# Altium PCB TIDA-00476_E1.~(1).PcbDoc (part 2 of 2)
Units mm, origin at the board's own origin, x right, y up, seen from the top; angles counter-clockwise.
Board outline 85.09 x 49.91 mm, 2 copper layers (Top Layer, Bottom Layer), stack 1.575 mm thick; 132 components, 75 nets, 329 pads, 292 vias.
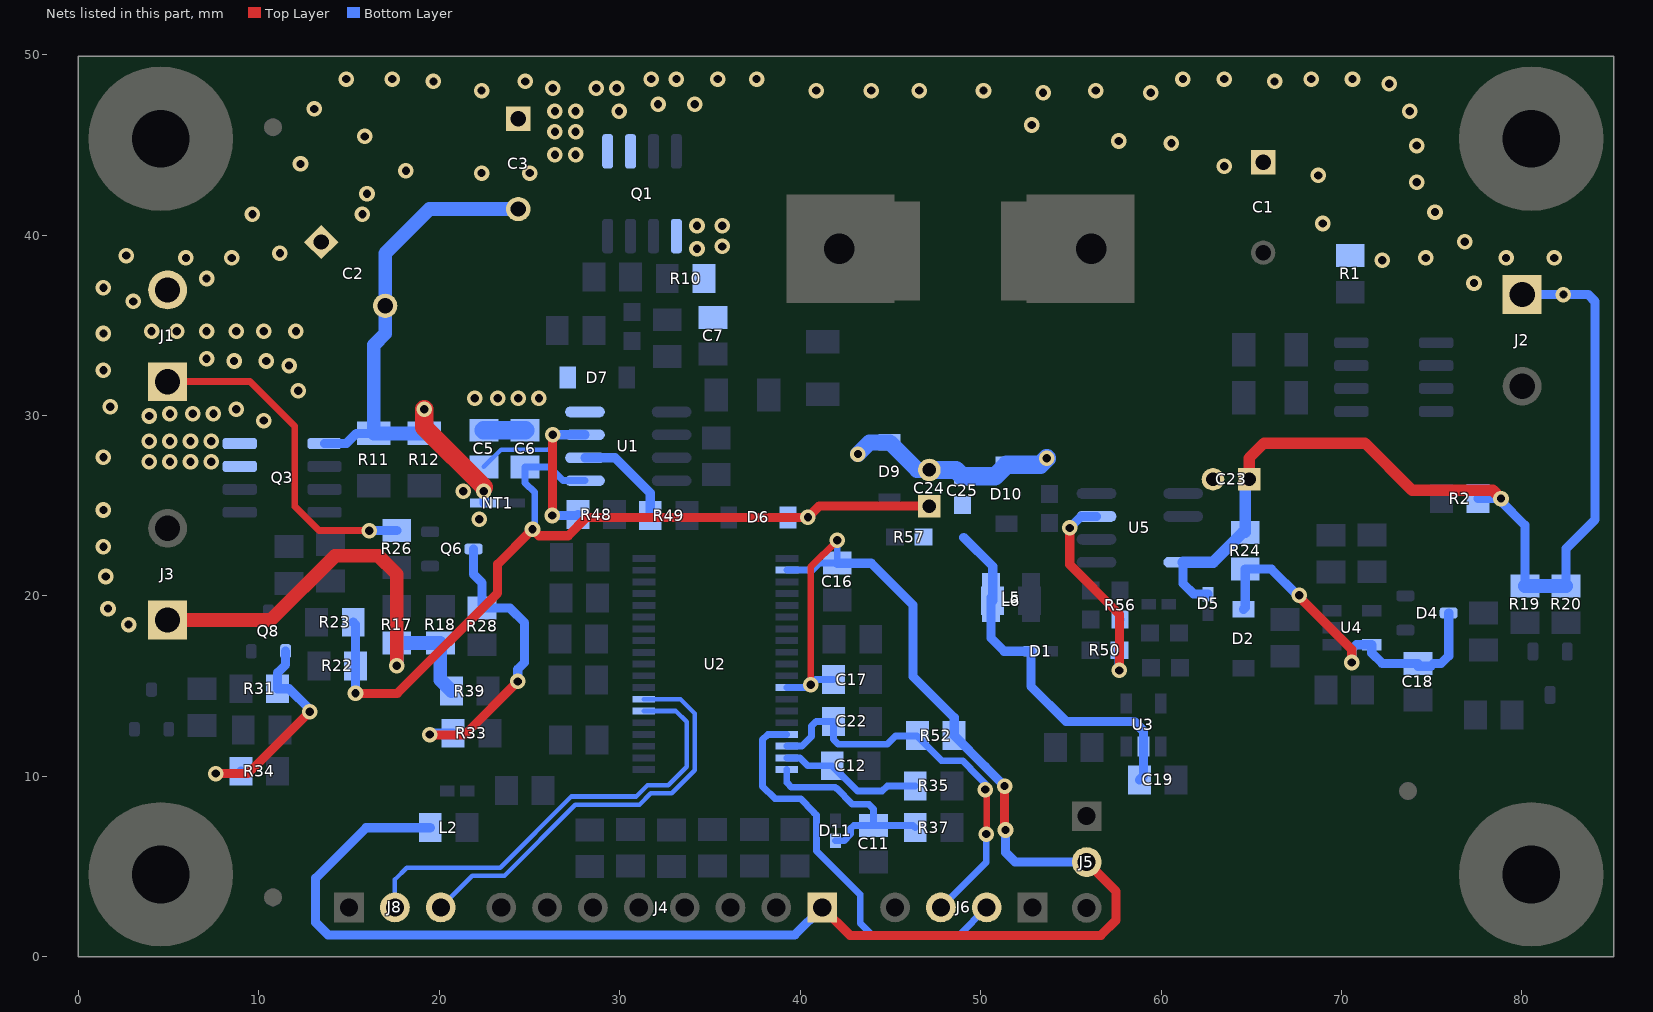
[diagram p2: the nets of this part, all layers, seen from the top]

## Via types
v1: diameter 0.864, hole 0.457, Top Layer to Bottom Layer, 292 vias

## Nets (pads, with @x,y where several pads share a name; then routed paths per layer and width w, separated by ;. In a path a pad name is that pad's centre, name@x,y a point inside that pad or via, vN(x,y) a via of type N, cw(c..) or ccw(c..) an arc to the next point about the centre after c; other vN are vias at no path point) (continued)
NetR50_2: R50.2 R56.2 U5.3 | length 13.6
  Top Layer w0.508: v1(54.939,23.774) 54.939,21.743 57.696,18.987 57.696,16.015 57.709,16.002 57.709,15.951 57.683,15.926 v1(57.683,15.875)
  Bottom Layer w0.508: v1(54.939,23.774) 55.574,24.409 U5.3@56.426,24.409 ; v1(57.683,15.875) 57.683,16.98 R50.2@57.696,16.993 57.696,18.656 R56.2@57.734,18.695
P1.1: J8.2 U2.6 | length 25.4
  Bottom Layer w0.254: J8.2@17.551,2.743 17.551,4.293 18.209,4.95 23.383,4.95 27.323,8.89 30.922,8.89 31.548,9.515 32.699,9.515 33.712,10.529 33.712,13.03 33.115,13.627 U2.6@31.339,13.627
P1.2: J8.3 U2.7 | length 23.5
  Bottom Layer w0.254: J8.3@20.091,2.743 21.844,4.496 23.622,4.496 27.553,8.426 31.101,8.426 31.736,9.061 32.887,9.061 34.166,10.341 34.166,13.487 33.376,14.277 U2.7@31.339,14.277
P1.5: C12.1 R35.2 U2.37 | length 8
  Bottom Layer w0.381: U2.37@39.263,11.029 40,11.029 40.437,10.592 C12.1@41.783,10.592 43.18,9.195 44.552,9.195 44.831,9.474 R35.2@46.38,9.474
P3.6: C11.1 D11.2 R37.1 U2.38 | length 12
  Bottom Layer w0.381: U2.38@39.263,10.376 39.263,9.657 39.519,9.401 41.927,9.401 41.981,9.347 42.012,9.347 42.901,8.458 43.815,8.458 44.069,8.204 C11.1@44.069,7.29 ; D11.2@41.961,6.435 42.427,6.435 42.799,6.807 42.799,7.112 42.977,7.29 C11.1@44.069,7.29 ; R37.1@46.38,7.163 46.253,7.29 C11.1@44.069,7.29
P+: C1.1 C2.1 C3.1 C23.1 D5.2 J1.2 J2.1 J3.1 Q1.5 Q1.6 R1.2 R2.2 R17.2 R18.2 R19.2 R20.2 R24.2 R39.1 U5.8 | length 82.7
  Top Layer w0.635: C23.1@64.881,26.467 64.881,27.645 65.71,28.473 71.298,28.473 73.914,25.857 78.384,25.857 v1(78.842,25.4)
  Top Layer w0.762: J3.1@4.953,18.669 10.668,18.669 14.224,22.225 16.637,22.225 17.653,21.209 v1(17.653,16.129)
  Bottom Layer w0.508: U5.8@61.226,21.869 61.226,20.689 61.807,20.108 D5.2@62.611,20.108 ; R2.2@77.572,25.4 78.689,25.4 v1@78.842,25.248 ; v1(78.842,25.4) v1@78.842,25.248 ; J2.1@80.01,36.703 v1(82.296,36.703) 83.671,36.703 84.052,36.322 84.052,24.235 82.448,22.631 R20.2@82.448,20.549 ; R19.2@80.162,20.549 80.162,23.927 v1@78.842,25.248
  Bottom Layer w0.635: U5.8@61.226,21.869 62.882,21.869 64.533,23.52 R24.2@64.668,23.52 64.668,26.254 C23.1@64.881,26.467
  Bottom Layer w0.762: v1(17.653,16.129) R17.2@17.653,17.399 R18.2@20.066,17.399 20.066,15.342 R39.1@20.676,14.732 ; R19.2@80.162,20.549 R20.2@82.448,20.549
  other v1: 2.794,18.415 1.651,19.304 1.524,21.082 1.397,22.733 1.397,24.765 1.397,27.686 1.778,30.48 1.397,32.512 1.397,34.544 3.048,36.322 1.397,37.084 77.343,37.338 7.112,37.592 72.263,38.608 5.969,38.735 8.509,38.735 74.676,38.735 79.121,38.735 81.788,38.735 2.667,38.862 11.176,38.989 76.835,39.624 68.961,40.64 9.652,41.148 15.748,41.148 75.184,41.275 16.002,42.291 74.168,42.926 68.707,43.307 22.352,43.434 25.019,43.434 18.161,43.561 63.5,43.815 12.319,43.942 26.416,44.45 27.559,44.45 74.168,44.958 60.579,45.085 57.658,45.212 15.875,45.466 26.416,45.72 27.559,45.72 52.832,46.101 26.416,46.863 27.559,46.863 29.972,46.863 73.787,46.863 13.081,46.99 32.131,47.244 34.163,47.244 53.467,47.879 59.436,47.879 22.352,48.006 40.894,48.006 43.942,48.006 46.609,48.006 50.165,48.006 56.388,48.006 26.289,48.133 28.702,48.133 29.845,48.133 72.644,48.387 19.685,48.514 24.765,48.514 66.294,48.514 14.859,48.641 17.399,48.641 31.75,48.641 33.147,48.641 35.433,48.641 37.592,48.641 61.214,48.641 63.5,48.641 68.326,48.641 70.612,48.641
P-: J1.1 Q3.7 Q3.8 R26.1 | length 18.7
  Top Layer w0.381: J1.1@4.953,31.877 9.525,31.877 12.002,29.4 12.002,24.956 13.335,23.622 v1(16.129,23.622)
  Bottom Layer w0.508: v1(16.129,23.622) R26.1@17.653,23.622
  other v1: 3.937,27.432 5.08,27.432 6.223,27.432 7.366,27.432 3.937,28.575 5.08,28.575 6.223,28.575 7.366,28.575 10.287,29.718 3.937,29.972 5.08,30.099 6.35,30.099 7.493,30.099 8.763,30.353 12.192,31.369 11.684,32.766 8.636,33.02 10.414,33.02 7.112,33.147 4.064,34.671 5.461,34.671 7.112,34.671 8.763,34.671 10.287,34.671 12.065,34.671
P_EN: Q8.1 R31.2 R34.1 | length 12.7
  Top Layer w0.508: v1(7.62,10.16) 9.398,10.16 v1(12.827,13.589)
  Bottom Layer w0.508: v1(7.62,10.16) 8.89,10.16 R34.1@9.017,10.287 ; Q8.1@11.491,16.934 11.491,16.19 11.049,15.748 R31.2@11.049,14.859 11.684,14.859 12.827,13.716 v1(12.827,13.589)
P_V: Q6.3 R28.2 R33.1 | length 17
  Top Layer w0.508: v1(19.482,12.319) 19.507,12.294 21.387,12.294 v1(24.359,15.265)
  Bottom Layer w0.508: v1(19.482,12.319) 19.558,12.395 R33.1@20.777,12.395 ; Q6.3@21.901,22.606 21.901,21.203 22.377,20.726 R28.2@22.377,19.329 23.927,19.329 24.736,18.52 24.736,16.321 24.359,15.943 v1(24.359,15.265)
PGND: C2.2 C3.2 C5.2 C6.2 C7.2 C23.2 C24.2 C25.2 D7.2 D9.2 D10.2 NT1.2 Q1.1 Q3.1 R10.1 R11.2 R12.2 U1.4 | length 46.5
  Top Layer w1.016: v1(19.177,30.353) 19.177,29.337 v1@22.479,26.035
  Bottom Layer w0.508: Q3.1@13.653,28.448 14.859,28.448 15.42,29.009 R11.2@16.383,29.009 ; NT1.2@22.479,25.146 v1(22.479,25.806) v1@22.479,26.035
  Bottom Layer w0.762: v1(19.177,30.353) R12.2@19.177,29.009 R11.2@16.383,29.009 16.383,33.909 17.008,34.534 C2.2@17.008,36.078 17.008,38.979 19.471,41.442 C3.2@24.384,41.442
  Bottom Layer w0.889: v1(43.205,27.864) 43.852,28.511 D9.2@44.958,28.511 46.484,26.984 C24.2@47.168,26.984
  Bottom Layer w1.016: C5.2@22.479,29.185 C6.2@24.765,29.185 ; C24.2@47.168,26.984 48.644,26.984 C25.2@48.997,26.632 50.801,26.632 D10.2@51.435,27.266 53.301,27.266 v1@53.664,27.629
  other v1: 22.225,24.257 21.336,25.806 53.67,27.635 21.971,30.963 23.241,30.963 24.384,30.963 25.527,30.963 34.29,39.243 35.687,39.37 34.29,40.513 35.687,40.513
PW_H: R49.1 U1.2 | length 5.7
  Bottom Layer w0.508: U1.2@28.08,27.661 29.744,27.661 31.699,25.705 R49.1@31.699,24.46
PW_L: C5.1 R48.1 U1.3 | length 12.6
  Top Layer w0.508: v1(26.264,24.46) 26.289,24.486 v1(26.289,28.931)
  Bottom Layer w0.254: C5.1@22.479,27.153 23.441,28.115 26.035,28.115 26.289,28.369 v1(26.289,28.931)
  Bottom Layer w0.508: v1(26.264,24.46) 27.635,24.46 R48.1@27.686,24.511 ; v1(26.289,28.931) U1.3@28.08,28.931
RST: C22.1 J6.3 R52.2 U2.36 | length 22.2
  Top Layer w0.381: v1(50.267,9.271) 50.343,9.195 50.343,6.833 v1(50.317,6.807)
  Bottom Layer w0.381: U2.36@39.263,11.679 40.102,11.679 40.64,12.217 40.64,12.802 40.894,13.056 C22.1@41.859,13.056 41.859,12.062 42.139,11.782 44.828,11.782 45.279,12.233 46.473,12.233 47.835,10.871 49.003,10.871 49.438,10.436 49.438,10.405 50.267,9.576 v1(50.267,9.271) ; J6.3@47.803,2.743 50.317,5.258 v1(50.317,6.807)
TEST: J6.2 U2.35 | length 22.6
  Bottom Layer w0.381: U2.35@39.263,12.329 38.212,12.329 37.922,12.04 37.922,9.449 38.605,8.766 40.027,8.766 40.758,8.036 40.758,8.017 40.916,7.858 40.916,7.832 40.916,5.871 43.332,3.454 43.332,1.88 44.018,1.194 48.793,1.194 J6.2@50.343,2.743
V+: C18.1 D2.1 D4.3 R24.1 U4.5 | length 20.4
  Top Layer w0.508: v1@67.564,20.041 70.568,17.037 v1(70.568,16.313)
  Bottom Layer w0.508: D2.1@64.567,19.265 64.668,19.367 R24.1@64.668,21.488 66.116,21.488 67.564,20.041 v1(67.666,20.041) ; v1(70.568,16.313) 70.568,17.037 70.828,17.297 U4.5@71.679,17.297 71.679,16.84 72.256,16.263 C18.1@74.234,16.263 ; C18.1@74.234,16.104 74.948,16.104 75.108,16.263 75.522,16.263 75.942,16.684 D4.3@75.942,19.057
VCC: C6.1 C19.1 C24.1 C25.1 D1.2 D6.2 L5.2 L6.2 R22.2 R23.2 R57.2 U1.1 U3.2 | length 70.6
  Top Layer w0.508: v1(15.367,14.605) 17.678,14.605 23.241,20.168 23.241,21.768 v1@25.048,23.574 ; v1(25.171,23.698) 25.527,23.343 27.153,23.343 28.169,24.359 v1(40.437,24.359) 41.062,24.984 C24.1@47.168,24.984
  Bottom Layer w0.381: v1(25.171,23.698) 25.298,23.825 25.298,25.73 24.765,26.264 C6.1@24.765,27.153 26.111,27.153 26.873,26.391 U1.1@28.08,26.391
  Bottom Layer w0.508: R23.2@15.24,18.542 15.367,18.415 R22.2@15.367,16.129 v1(15.367,14.605) ; D6.2@39.331,24.359 v1(40.437,24.359) ; 49.073,23.241 50.673,21.641 L6.2@50.673,19.736 ; L5.2@50.589,19.914 50.571,19.896 50.571,17.678 51.308,16.942 D1.2@52.79,16.942 52.79,15.003 54.744,13.048 58.503,13.048 59.03,12.522 U3.2@59.03,11.652 59.03,10.033 C19.1@58.801,9.804
VDD: C16.1 C17.1 J4.1 J5.2 L2.1 R52.1 U2.21 U2.31 | length 101.4
  Top Layer w0.381: v1(40.589,15.088) 40.589,21.615 v1(42.062,23.089)
  Top Layer w0.508: J4.1@41.224,2.735 42.765,1.194 56.667,1.194 57.506,2.032 57.506,3.632 J5.2@55.88,5.258 ; v1(51.333,9.468) 51.333,7.087 v1(51.384,7.036)
  Bottom Layer w0.381: U2.31@39.263,14.93 40.432,14.93 v1(40.589,15.088) 40.869,15.367 C17.1@41.859,15.367 ; U2.21@39.266,21.433 40.686,21.433 41.072,21.819 C16.1@42.062,21.819 v1(42.062,23.089)
  Bottom Layer w0.508: L2.1@19.507,7.163 15.951,7.163 13.157,4.369 13.157,1.905 13.843,1.219 39.709,1.219 J4.1@41.224,2.735 ; C16.1@42.062,21.819 43.942,21.819 46.253,19.507 46.253,15.545 48.539,13.259 R52.1@48.539,12.268 50.27,10.538 50.27,10.532 v1(51.333,9.468) ; v1(51.384,7.036) 51.384,5.791 51.918,5.258 J5.2@55.88,5.258
pads on no net: FID1.1 FID2.1 FID3.1 FID4.1 FID5.1 FID6.1 H1.1 H2.1 H3.1 H4.1 LBL1.0 U2.10 U2.11 U2.12 U2.13 U2.14 U2.15 U2.17 U2.18 U2.19 U2.32 U2.33 U2.34 U3.4 U3.5 U5.5 U5.6

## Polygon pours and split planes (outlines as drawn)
NetL1_1 on Top Layer "Bottom Layer-No Net" (solid, remove dead copper, pour order 31): 31.496,45.466 31.496,41.91 32.004,41.402 36.068,41.402 36.703,40.767 36.703,39.751 36.703,33.884 37.211,33.376 48.743,33.376 49.276,33.909 49.276,44.323 47.625,45.974 35.179,45.974 32.004,45.974
PGND on Top Layer "Bottom Layer-No Net" (solid, remove dead copper, pour order 53): 21.336,32.512 21.336,30.709 21.463,30.582 21.488,30.607 27.686,30.607 35.306,30.607 35.433,30.607 36.068,31.242 36.195,31.369 36.195,37.084 36.195,40.716 35.89,41.021 35.763,41.148 32.385,41.148 28.702,41.148 28.194,41.148 27.94,40.894 27.559,40.513 27.559,38.354 27.559,35.306 26.797,34.544 25.146,32.893 21.717,32.893
P- on Top Layer "Bottom Layer-No Net" (solid, remove dead copper, pour order 52): 3.429,27.94 3.429,27.051 3.683,26.797 7.62,26.797 11.049,26.797 11.303,27.051 11.43,27.178 11.43,27.559 11.43,28.829 12.002,29.4 12.446,29.845 12.954,29.845 13.335,29.845 13.589,30.099 13.589,30.861 13.589,36.703 13.589,37.719 13.462,37.846 13.335,37.973 12.7,37.973 9.271,37.973 8.509,37.211 6.604,35.306 5.969,35.306 3.556,35.306 3.429,35.179 3.429,29.845
P+ on Top Layer "Bottom Layer-No Net" (solid, remove dead copper, pour order 50): 1.397,16.891 8.89,16.891 9.271,17.272 9.271,19.558 9.271,19.812 9.017,20.066 6.858,20.066 3.302,20.066 3.048,20.32 2.921,20.447 2.921,23.368 2.921,34.798 2.921,35.306 3.302,35.687 3.429,35.814 5.207,35.814 6.35,35.814 6.985,36.449 8.89,38.354 9.652,38.354 13.589,38.354 13.843,38.608 17.907,42.672 22.733,42.672 30.734,42.672 30.988,42.926 31.115,43.053 31.115,44.323 31.115,49.022 30.988,49.149 30.861,49.276 30.734,49.276 13.97,49.276 13.462,48.768 12.319,47.625 12.319,45.847 12.319,44.831 9.652,42.164 7.874,40.386 3.429,40.386 1.181,40.386 0.762,39.967 0.762,38.862 0.762,17.526
PGND on Top Layer "Bottom Layer-No Net" (solid, remove dead copper, pour order 48): 21.082,26.67 21.082,25.019 21.082,24.257 21.082,24.13 21.463,23.749 22.479,23.749 22.606,23.749 22.86,24.003 22.86,24.765 22.86,26.416 22.733,26.543 22.479,26.797 21.209,26.797
B- on Top Layer "Bottom Layer-No Net" (solid, remove dead copper, pour order 45): 66.802,34.671 66.802,33.147 66.802,29.972 66.929,29.845 67.056,29.718 69.088,29.718 71.501,29.718 71.628,29.845 71.628,30.353 71.628,30.607 71.501,30.734 71.12,30.734 69.723,30.734 69.596,30.861 69.342,31.115 69.342,31.242 69.342,32.004 69.469,32.131 69.596,32.258 70.358,32.258 71.501,32.258 71.755,32.512 71.755,33.02 71.755,33.147 71.628,33.274 70.739,33.274 69.723,33.274 69.469,33.528 69.342,33.655 69.342,34.29 69.342,34.417 69.342,35.179 69.342,35.814 69.215,35.941 67.818,35.941 67.056,35.941 66.802,35.687
NetJ2_2 on Top Layer "Bottom Layer-No Net" (solid, remove dead copper, pour order 37): 72.644,37.211 72.644,36.068 72.644,30.48 72.644,29.464 73.152,28.956 75.311,26.797 82.677,26.797 83.185,27.305 83.185,34.544 82.804,34.925 82.169,34.925 77.978,34.925 77.343,35.56 75.311,37.592 73.025,37.592
PGND on Top Layer "Bottom Layer-No Net" (solid, remove dead copper, pour order 43): 22.86,41.91 22.86,38.1 23.114,37.846 26.67,37.846 29.464,37.846 29.972,37.338 31.013,36.297 32.512,36.297 35.662,36.297 36.068,36.703 36.195,36.83 36.195,39.751 36.195,40.767 36.068,40.894 35.941,41.021 34.798,41.021 28.448,41.021 27.686,41.783 27.305,42.164 25.146,42.164 23.114,42.164 22.987,42.037
NetJ3_2 on Top Layer "Bottom Layer-No Net" (solid, remove dead copper, pour order 39): 3.429,26.259 3.429,24.638 3.429,20.828 3.556,20.701 3.81,20.447 6.604,20.447 10.033,20.447 10.287,20.701 10.414,20.828 10.414,22.479 10.414,23.662 10.795,24.043 11.43,24.678 11.43,25.4 11.43,26.035 11.176,26.289 9.144,26.289 3.459,26.289
B_S on Top Layer "Bottom Layer-No Net" (solid, remove dead copper, pour order 33): 51.054,42.926 51.054,38.735 51.054,33.02 51.054,30.353 51.054,30.097 51.308,29.843 56.515,29.843 65.276,29.843 65.405,29.972 65.659,30.226 65.659,32.893 65.659,37.084 66.802,38.227 66.802,39.116 66.802,40.386 66.294,40.894 65.913,41.275 63.5,41.275 61.087,41.275 60.071,42.291 59.055,43.307 51.435,43.307
P+ on Top Layer "Bottom Layer-No Net" (solid, remove dead copper, pour order 35): 82.55,39.37 83.185,38.735 83.185,35.814 82.804,35.433 80.137,35.433 78.105,35.433 75.438,38.1 69.596,38.1 68.707,38.989 68.707,42.545 68.326,42.926 61.976,42.926 60.198,44.704 52.197,44.704 50.165,46.736 31.369,46.736 31.09,46.457 30.48,46.736 26.162,46.736 24.511,45.085 22.225,45.085 21.971,45.339 21.971,48.768 22.479,49.276 73.152,49.276 74.803,47.625 74.803,43.18 78.613,39.37 80.137,39.37
GND on Top Layer "Top Layer-No Net 1" (solid, remove dead copper, pour order 58): 1.092,15.799 1.067,15.773 1.067,9.119 1.422,8.763 9.652,8.763 12.751,5.664 12.751,1.6 13.386,0.965 74.143,0.965 75.514,2.337 75.514,6.731 75.565,6.782 75.565,8.56 76.2,9.195 83.363,9.195 83.972,9.804 83.972,24.816 83.134,25.654 72.136,25.654 71.704,26.086 71.704,27.381 71.145,27.94 66.65,27.94 65.989,27.28 65.989,23.495 62.382,19.888 46.965,19.888 43.383,23.47 18.745,23.47 11.582,16.307 1.575,16.307 1.067,15.799
PGND on Top Layer "Top Layer-No Net" (solid, remove dead copper, pour order 56): 63.043,28.448 63.652,27.838 63.652,24.714 61.112,22.174 50.521,22.174 48.717,23.978 48.717,25.73 48.514,25.933 36.17,25.933 31.496,30.607 31.496,33.731 32.029,34.265 35.077,34.265 40.894,28.448
NetL1_1 on Bottom Layer "Bottom Layer-No Net" (solid, remove dead copper, pour order 30): 31.496,45.466 31.496,41.91 32.004,41.402 36.068,41.402 36.703,40.767 36.703,39.751 36.703,33.884 37.211,33.376 48.743,33.376 49.276,33.909 49.276,44.323 47.625,45.974 35.179,45.974 32.004,45.974
P- on Bottom Layer "Bottom Layer-No Net" (solid, remove dead copper, pour order 51): 3.429,27.94 3.429,27.051 3.683,26.797 7.62,26.797 11.049,26.797 11.303,27.051 11.43,27.178 11.43,27.559 11.43,28.829 12.002,29.4 12.446,29.845 12.954,29.845 13.335,29.845 13.589,30.099 13.589,30.861 13.589,36.703 13.589,37.719 13.462,37.846 13.335,37.973 12.7,37.973 9.271,37.973 8.509,37.211 6.604,35.306 5.969,35.306 3.556,35.306 3.429,35.179 3.429,29.845
PGND on Bottom Layer "Bottom Layer-No Net" (solid, remove dead copper, pour order 47): 21.082,26.67 21.082,25.019 21.082,24.257 21.082,24.13 21.463,23.749 22.479,23.749 22.606,23.749 22.86,24.003 22.86,24.765 22.86,26.416 22.733,26.543 22.479,26.797 21.209,26.797
B- on Bottom Layer "Bottom Layer-No Net" (solid, remove dead copper, pour order 44): 66.802,34.671 66.802,33.147 66.802,29.972 66.929,29.845 67.056,29.718 69.088,29.718 71.501,29.718 71.628,29.845 71.628,30.353 71.628,30.607 71.501,30.734 71.12,30.734 69.723,30.734 69.596,30.861 69.342,31.115 69.342,31.242 69.342,32.004 69.469,32.131 69.596,32.258 70.358,32.258 71.501,32.258 71.755,32.512 71.755,33.02 71.755,33.147 71.628,33.274 70.739,33.274 69.723,33.274 69.469,33.528 69.342,33.655 69.342,34.29 69.342,34.417 69.342,35.179 69.342,35.814 69.215,35.941 67.818,35.941 67.056,35.941 66.802,35.687
B_S on Bottom Layer "Bottom Layer-No Net" (solid, remove dead copper, pour order 32): 51.054,42.926 51.054,38.735 51.054,33.02 51.054,30.353 51.054,30.097 51.308,29.843 56.515,29.843 65.276,29.843 65.405,29.972 65.659,30.226 65.659,32.893 65.659,37.084 66.802,38.227 66.802,39.116 66.802,40.386 66.294,40.894 65.913,41.275 63.5,41.275 61.087,41.275 60.071,42.291 59.055,43.307 51.435,43.307
NetJ3_2 on Bottom Layer "Bottom Layer-No Net" (solid, remove dead copper, pour order 38): 3.429,26.259 3.429,24.638 3.429,20.828 3.556,20.701 3.81,20.447 6.604,20.447 10.033,20.447 10.287,20.701 10.414,20.828 10.414,22.479 10.414,23.662 10.795,24.043 11.43,24.678 11.43,25.4 11.43,26.035 11.176,26.289 9.144,26.289 3.459,26.289
PGND on Bottom Layer "Bottom Layer-No Net" (solid, remove dead copper, pour order 42): 32.893,40.894 32.766,40.767 32.766,39.243 32.766,38.989 32.893,38.862 33.274,38.862 33.655,38.481 33.655,38.354 33.655,36.83 33.655,35.179 34.036,34.798 35.941,34.798 36.322,35.179 36.322,38.862 36.322,40.64 35.941,41.021 33.02,41.021
L_S on Bottom Layer "Bottom Layer-No Net" (solid, remove dead copper, pour order 41): 12.7,26.289 12.573,26.162 12.573,25.527 12.573,25.4 13.208,24.765 20.32,24.765 20.447,24.892 20.447,27.305 20.32,27.432 19.304,27.432 18.034,27.432 15.621,27.432 15.113,26.924 14.732,26.543 14.478,26.289 13.589,26.289
PGND on Bottom Layer "Bottom Layer-No Net" (solid, remove dead copper, pour order 40): 12.7,28.829 12.7,28.067 12.827,27.94 15.494,27.94 19.939,27.94 20.066,27.94 20.32,28.194 20.387,28.261 20.387,29.059 20.387,37.786 21.082,38.481 26.543,38.481 27.178,38.481 27.686,38.989 27.686,41.148 27.686,42.037 27.305,42.418 24.892,42.418 19.05,42.418 17.653,41.021 14.097,37.465 14.097,29.083 13.97,28.956 12.954,28.956 12.827,28.956
NetJ2_2 on Bottom Layer "Bottom Layer-No Net" (solid, remove dead copper, pour order 36): 72.644,37.211 72.644,36.068 72.644,30.48 72.644,29.464 73.152,28.956 75.311,26.797 82.677,26.797 83.185,27.305 83.185,34.544 82.804,34.925 82.169,34.925 77.978,34.925 77.343,35.56 75.311,37.592 73.025,37.592
P+ on Bottom Layer "Bottom Layer-No Net" (solid, remove dead copper, pour order 49): 1.397,16.891 8.89,16.891 9.271,17.272 9.271,19.558 9.271,19.812 9.017,20.066 3.302,20.066 2.921,20.447 2.921,35.306 3.429,35.814 6.35,35.814 8.89,38.354 13.589,38.354 18.161,42.926 30.175,42.926 31.115,43.866 31.115,49.022 30.861,49.276 13.97,49.276 12.319,47.625 12.319,44.831 7.874,40.386 1.181,40.386 0.762,39.967 0.762,38.862 0.762,17.526
NetL1_1 on Bottom Layer "Bottom Layer-No Net 1" (solid, remove dead copper, pour order 54): 29.769,35.306 29.921,35.154 31.217,35.154 31.376,35.313 31.376,40.998 31.78,41.402 34.976,41.402 35.255,41.681 35.255,44.196 34.925,44.526 31.953,44.526 31.496,44.069 31.496,43.485 30.455,42.443 30.048,42.443 29.743,42.139 29.743,36.652 29.769,36.627
PGND on Bottom Layer "Bottom Layer-No Net" (solid, remove dead copper, pour order 46): 21.209,28.423 21.336,28.296 25.654,28.296 25.781,28.423 25.781,29.566 26.035,29.82 29.083,29.82 29.21,29.947 29.21,31.191 27.61,32.791 21.615,32.791 21.209,32.385
VCC on Bottom Layer "Bottom Layer-No Net 2" (solid, remove dead copper, pour order 55): 46.228,25.603 46.228,23.927 46.228,22.835 46.457,22.606 46.634,22.428 47.244,22.428 49.809,22.428 49.86,22.479 49.962,22.581 49.962,24.536 49.962,25.273 49.632,25.603 49.555,25.679 48.463,25.679 46.431,25.679 46.228,25.476
P+ on Bottom Layer "Bottom Layer-No Net" (solid, remove dead copper, pour order 34): 82.55,39.37 83.185,38.735 83.185,35.814 82.804,35.433 80.137,35.433 78.105,35.433 75.438,38.1 69.596,38.1 68.707,38.989 68.707,42.545 68.326,42.926 61.976,42.926 60.198,44.704 52.197,44.704 50.165,46.736 31.369,46.736 31.09,46.457 30.48,46.736 26.162,46.736 24.511,45.085 22.225,45.085 21.971,45.339 21.971,48.768 22.479,49.276 73.152,49.276 74.803,47.625 74.803,43.18 78.613,39.37 80.137,39.37
GND on Bottom Layer "Top Layer-No Net 1" (solid, remove dead copper, pour order 57): 1.092,15.799 1.067,15.773 1.067,9.119 1.422,8.763 9.652,8.763 12.751,5.664 12.751,1.6 13.386,0.965 74.143,0.965 75.514,2.337 75.514,6.731 75.565,6.782 75.565,8.56 76.2,9.195 83.363,9.195 83.972,9.804 83.972,24.816 83.134,25.654 72.136,25.654 71.704,26.086 71.704,27.381 71.145,27.94 66.65,27.94 65.989,27.28 65.989,23.495 62.382,19.888 46.431,19.888 42.85,23.47 18.745,23.47 11.582,16.307 1.575,16.307 1.067,15.799

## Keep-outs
Keep-Out Layer:
  lines w0.152: 0.508,0.508 84.582,0.508 84.582,49.403 0.508,49.403 0.508,0.508

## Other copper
Top Layer:
  text ".Layer_Name" at 18.694,-21.666 h1.52
Bottom Layer:
  text ".Layer_Name" at 19.761,-21.844 h1.52
Multi-Layer:
  pour cut-out: 49.327,15.134 49.581,14.889 61.926,14.889 62.205,15.137 62.205,21.401 61.886,21.645 49.378,21.645 49.327,21.594

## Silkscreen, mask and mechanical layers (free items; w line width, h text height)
Top Overlay:
  circle w0.254: c38.354,41.656 r0.284
  text "+" at 74.6,37.363 h0.89
  text "+" at 9.703,35.154 h0.89
  text "+" at 10.058,18.288 h0.89
  text "TIDA-00476-E1" at 50.775,17.526 h1.52
  text ".Layer_Name" at 16.739,-21.946 h1.52
Bottom Overlay:
  circle w0.152: c54.966,21.793 r0.127
  circle w0.152: c68.301,16.205 r0.114
  circle w0.152: c60.935,11.481 r0.163
  circle w0.152: c18.694,15.062 r0.614
  circle w0.152: c19.38,34.341 r0.614
  lines w0.152: 8.128,17.145 8.763,16.51 8.763,16.256 ; 10.414,19.939 10.414,23.749 10.541,23.749 ; 11.176,19.558 11.811,19.558 12.065,19.304 12.065,19.05 ; 12.065,17.653 12.065,17.399 12.192,17.272 12.319,17.272 ; 12.7,24.13 14.859,24.13 15.621,24.892 20.955,24.892 21.463,24.384 21.59,24.257 21.59,23.749 21.844,23.495 22.352,23.495 22.772,23.075 22.772,22.962 22.772,20.74 23.355,20.74 23.673,20.422 23.673,19.608 ; 16.129,14.884 16.129,14.3 16.231,14.199 16.231,14.072 ; 16.231,17.399 16.383,17.399 ; 16.434,17.348 16.434,16.434 16.764,16.104 17.018,16.104 ; 18.466,16.078 20.472,16.078 ; 21.92,16.104 23.419,16.104 ; 23.673,17.475 23.673,18.237 ; 25.197,24.816 25.679,24.816 25.959,25.095 26.619,25.095 ; 27.127,36.373 27.28,36.373 27.432,36.22 29.82,36.22 ; 34.773,25.552 34.773,25.603 34.849,25.679 36.932,25.679 37.897,26.645 ; 57.252,21.082 57.252,21.158 57.125,21.285 54.94,21.285 ; 61.9,17.526 62.128,17.297 62.128,17.17 62.128,17.094 ; 62.992,21.234 62.992,21.92 ; 70.002,12.878 70.002,12.979 70.256,13.233 70.256,13.691 ; 54.94,21.285 54.94,21.26 55.016,21.184 55.016,21.387 54.94,21.311 54.94,21.285 ; 18.034,35.509 18.263,35.281 23.927,35.281 24.206,35.56 24.206,40.03 23.724,40.513 18.212,40.513 18.034,40.335 18.034,35.509 ; 30.378,9.449 30.378,22.784 40.284,22.784 40.284,9.449 30.505,9.449 30.378,9.449
  text "a" at 19.736,34.138 h0.89
  text "a" at 19.05,14.859 h0.89
  text ".Layer_Name" at 16.916,-21.666 h1.52
Top Paste:
  text ".Layer_Name" at 21.006,-21.666 h1.52
Bottom Paste:
  text ".Layer_Name" at 23.495,-21.59 h1.52
Top Solder:
  text ".Layer_Name" at 20.828,-21.844 h1.52
Bottom Solder:
  text ".Layer_Name" at 25.806,-21.946 h1.52
Drill Guide:
  text ".Layer_Name" at 24.562,-21.666 h1.52
M1 Board Outline:
  the board outline again, w0.254
  text ".layer_Name" at 19.456,-21.361 h0.89
M2 Board Dimensions:
  rectangle: 3.175,-10.16 12.7,-6.985
  rectangle: 0,-6.985 3.175,-3.81
  lines w0.178: 0,-6.985 25.4,-6.985 ; 3.175,-10.16 3.175,-3.81 ; 6.35,-10.16 6.35,-3.81 ; 12.7,-10.16 12.7,-3.81 ; 19.05,-10.16 19.05,-3.81 ; 0,-10.16 0,-3.81 25.4,-3.81 25.4,-10.16 0,-10.16
M3 3D STEP Top:
  text ".Layer_Name" at 20.472,-21.946 h1.52
M4 3D STEP Bottom:
  text ".Layer_Name" at 18.872,-22.022 h1.52
M5 Assembly Top:
  circle w0.254: c55.956,7.798 r0.284
  circle w0.254: c53.086,3.302 r0.284
  circle w0.254: c37.338,2.921 r0.284
  circle w0.254: c14.732,2.921 r0.284
  circle w0.254: c44.069,44.069 r0.284
  circle w0.254: c41.656,41.402 r0.284
  circle w0.254: c40.005,47.752 r0.284
  lines w0.254: -7.417,-23.626 160.223,-23.626 ; -7.417,-18.462 160.274,-18.462 ; -7.417,-13.297 -7.417,-28.791 94.31,-28.791 160.274,-28.791 160.274,-13.297 -7.404,-13.297 -7.404,-28.791 32.614,-28.791 ; 55.194,-28.791 55.194,-13.297 ; 87.376,-18.462 87.376,-13.297 ; 108.712,-18.462 108.712,-13.297 ; 124.511,-28.956 124.511,-23.804
  text "COMPONENTS MARKED 'DNP' SHOULD NOT BE POPULATED." at 29.299,-8.09 h1.52
  text "ASSEMBLY VARIANT:" at 29.286,-11.024 h1.52
  text ".VariantName" at 55.601,-11.024 h1.52
  text "SVN REV:" at 112.014,-16.637 h1.52
  text "PCB VIEWED FROM TOP SIDE" at -5.804,-16.654 h1.52
  text "BOARD #:" at 57.099,-16.654 h1.52
  text ".PRJ_Number" at 70.955,-16.654 h1.52
  text "REV:" at 92.405,-16.654 h1.52
  text ".PCB_Rev" at 99.809,-16.654 h1.52
  text ".VersionControl_RevNumber" at 124.206,-16.764 h1.52
  text ".Layer_Name" at 16.205,-21.768 h1.52
  text "LAYER NAME =" at -5.867,-21.92 h1.52
  text "PLOT NAME=" at -5.804,-27.034 h1.52
  text "TEXAS INSTRUMENTS" at 129.87,-27.034 h1.52
  text ".plot_File_Name" at 9.55,-27.127 h1.52
  text "GENERATED    :" at 68.948,-27.127 h1.52
  text ".Print_Date" at 91.034,-27.127 h1.52
  text ".Print_Time" at 109.55,-27.127 h1.52
M6 Assembly Bottom:
  circle w0.254: c28.956,26.518 r0.18
  circle w0.254: c20.447,21.717 r0.127
  circle w0.254: c11.557,17.907 r0.18
  circle w0.254: c5.055,13.437 r0.127
  circle w0.254: c80.67,16.002 r0.127
  circle w0.254: c74.447,18.059 r0.127
  circle w0.254: c57.658,21.92 r0.217
  circle w0.152: c59.944,12.395 r0.18
  lines w0.152: 29.58,25.796 29.58,30.796 31.38,30.796 31.38,25.796 29.58,25.796
  lines w0.254: -7.429,-18.474 160.261,-18.474 ; -7.379,-23.639 160.261,-23.639 ; 28.334,-28.969 28.334,-23.817 ; 44.133,-18.474 44.133,-13.31 ; 65.468,-18.474 65.468,-13.31 ; 97.65,-28.804 97.65,-13.31 ; 120.231,-28.804 160.249,-28.804 160.249,-13.31 -7.429,-13.31 -7.429,-28.804 58.534,-28.804 160.261,-28.804 160.261,-13.31
  text "COMPONENTS MARKED 'DNP' SHOULD NOT BE POPULATED." at 154.991,-8.077 h1.52
  text ".VariantName" at 128.473,-11.024 h1.52
  text "ASSEMBLY VARIANT:" at 154.864,-11.024 h1.52
  text ".VersionControl_RevNumber" at 26.302,-16.667 h1.52
  text "SVN REV:" at 39.154,-16.667 h1.52
  text ".PCB_Rev" at 53.035,-16.667 h1.52
  text "REV:" at 60.439,-16.667 h1.52
  text ".PRJ_Number" at 81.89,-16.667 h1.52
  text "BOARD #:" at 95.745,-16.667 h1.52
  text "PCB VIEWED FROM BOTTOM SIDE" at 158.648,-16.667 h1.52
  text ".Layer_Name" at 43.713,-21.946 h1.52
  text "LAYER NAME =" at 63.678,-22.047 h1.52
  text "TEXAS INSTRUMENTS" at 22.974,-27.047 h1.52
  text "PLOT NAME =" at 158.648,-27.047 h1.52
  text ".Print_Time" at 44.501,-27.076 h1.52
  text ".Print_Date" at 63.017,-27.076 h1.52
  text "GENERATED    :" at 85.103,-27.076 h1.52
  text ".plot_File_Name" at 141.961,-27.127 h1.52
M9 Title Sheet:
  drawing of 56 lines, arcs and shapes, not listed
  text "1" at 18.792,204.127 h1.14
  text "2" at 82.182,204.127 h1.14
  text "3" at 145.411,204.127 h1.14
  text "4" at 209.08,204.127 h1.14
  text "5" at 272.555,204.127 h1.14
  text "6" at 336.182,204.127 h1.14
  text "A" at -10.579,175.095 h1.14
  text "A" at 365.341,175.095 h1.14
  text "B" at -10.579,114.643 h1.14
  text "B" at 365.341,114.643 h1.14
  text "C" at -10.579,54.318 h1.14
  text "C" at 365.341,54.318 h1.14
  text "PROJECT TITLE:" at 288.125,7.048 h1.52
  text ".PRJ_Title" at 289.395,3.662 h1.52
  text "DESIGNED FOR:" at 288.125,-0.597 h1.52
  text ".PRJ_Customer" at 289.395,-4.153 h1.52
  text "D" at -10.579,-5.88 h1.14
  text "D" at 365.341,-5.88 h1.14
  text "FILE NAME:" at 288.125,-8.217 h1.52
  text ".PCB_File_Name_No_Path" at 289.395,-11.265 h1.52
  text "Texas Instruments (TI) and/or its licensors do not warrant the accuracy or completeness of this specification" at 161.9,-15.376 h1.14
  text "ENGINEER:" at 288.125,-15.583 h1.52
  text "LAYOUT BY:" at 326.352,-15.583 h1.52
  text "or any information contained therein. TI and/or its licensors do not warrant that this design will meet" at 160.757,-18.237 h1.14
  text ".PRJ_Engineer" at 289.395,-19.52 h1.52
  text ".PCB_Layout" at 327.635,-19.52 h1.52
  text "the specifications, will be suitable for your application or fit for any particular purpose, or will operate in" at 160.757,-21.099 h1.14
  text "ALTIUM DESIGNER VERSION:" at 326.352,-23.457 h1.52
  text "an implementation. TI and/or its licensors do not warrant that the design is production worthy. You should" at 160.757,-23.961 h1.14
  text "completely validate and test your design implementation to confirm the system functionality for your application." at 161.9,-26.822 h1.14
  text ".print_Scale" at 289.395,-26.843 h1.52
  text ".Application_BuildNumber" at 327.635,-26.843 h1.52
  text "1" at 18.792,-32.093 h1.14
  text "2" at 82.182,-32.093 h1.14
  text "3" at 145.411,-32.093 h1.14
  text "4" at 209.08,-32.093 h1.14
  text "5" at 272.555,-32.093 h1.14
  text "6" at 336.182,-32.093 h1.14
M10 Fab Notes:
  drawing of 228 lines, arcs and shapes, not listed
  text "DESIGN INFORMATION" at 312.449,159.36 h1.52
  text "(REFER ALSO ARRAY/PANEL PROFILING INFORMATION)" at 306.161,155.811 h1.52
  text "BOARD SIZE" at 288.737,155.702 h1.52
  text "X" at 313.324,152.455 h1.52
  text "85.09MM" at 298.958,152.4 h1.52
  text "49.91MM" at 318.516,152.4 h1.52
  text "2" at 326.038,149.454 h1.52
  text "Number of Layers :" at 298.098,149.047 h1.52
  text "8" at 325.12,146.177 h1.52
  text "MIN. TRACK WIDTH:" at 298.119,146.161 h1.52
  text "MIL" at 329.894,146.161 h1.52
  text "MIN. CLEARANCE:" at 298.119,142.808 h1.52
  text "7.874" at 323.063,142.723 h1.52
  text "MIL" at 330.302,142.697 h1.52
  text "MIN. VIA PAD SIZE:" at 298.119,139.455 h1.52
  text "MIL" at 329.894,139.455 h1.52
  text "34" at 324.866,139.192 h1.52
  text "0.203mm (8MIL)" at 315.772,135.856 h1.52
  text "EXTERNAL" at 333.629,135.763 h1.52
  text "MINIMUM ANNULAR RING" at 289.756,135.747 h1.52
  text "PER" at 294.836,132.75 h1.52
  text "IPC-D-275 CLASS 2 LEVEL C" at 300.424,132.75 h1.52
  text "MIL, HOLES" at 338.225,129.898 h1.52
  text "+/-" at 328.257,129.88 h1.52
  text "+/-" at 349.948,129.88 h1.52
  text "REGISTRATION TOLERANCES:" at 289.756,129.753 h1.52
  text "METAL" at 320.231,129.753 h1.52
  text "5" at 334.866,129.753 h1.52
  text "3" at 356.024,129.753 h1.52
  text "MIL" at 358.977,129.753 h1.52
  text "MATERIAL:" at 287.857,126.083 h1.52
  text "FR-4 High Tg" at 312.913,122.519 h1.52
  text "FR-408" at 298.551,122.301 h1.52
  text "OTHER" at 336.346,122.301 h1.52
  text "X" at 308.918,122.123 h1.52
  text "63 MIL (1.6mm) +/-10%" at 306.681,118.168 h1.52
  text "THICKNESS:" at 289.756,118.059 h1.52
  text "X" at 303.426,118.059 h1.52
  text "OTHER" at 339.318,118.059 h1.52
  text "TOLERANCE:" at 289.756,114.046 h1.52
  text "X" at 311.075,114.046 h1.52
  text "ANSI IPC-6012 TYPE 3 CLASS 2" at 315.823,114.046 h1.52
  text "OTHER +/-" at 315.823,110.084 h1.52
  text "BOW & TWIST:" at 289.756,106.096 h1.52
  text "X" at 311.075,106.096 h1.52
  text "ANSI IPC-6012 TYPE 3 CLASS 2" at 315.823,106.096 h1.52
  text "OTHER +/-" at 315.823,102.07 h1.52
  text "COPPER THICKNESS (FINISHED):" at 287.782,99.06 h1.52
  text "1.4MIL (1oz)" at 308.571,96.493 h1.52
  text "2MIL (1.4oz)" at 328.053,96.493 h1.52
  text "2.8MIL (2oz)" at 346.518,96.493 h1.52
  text "OUTER:" at 295.287,96.384 h1.52
  text "X" at 305.308,96.368 h1.52
  text "1.4MIL (1oz)" at 308.698,92.505 h1.52
  text "2.8MIL (2oz)" at 328.18,92.505 h1.52
  text "N/A" at 346.634,92.514 h1.52
  text "INNER SIGNAL:" at 288.071,92.396 h1.52
  text "X" at 343.535,92.253 h1.52
  text "DRILLING:" at 288.163,89.281 h1.52
  text "X" at 306.729,87.325 h1.52
  text "AS SHOWN" at 311.479,87.325 h1.52
  text "X" at 329.615,87.325 h1.52
  text "NC_DRILL FILES" at 333.095,87.325 h1.52
  text "REFERENCE:" at 292.608,86.868 h1.52
  text "PTH MIN COPPER THICKNESS:" at 290.264,83.312 h1.52
  text "X" at 324.56,83.312 h1.52
  text "1MIL" at 328.04,83.312 h1.52
  text "OTHER" at 340.664,83.312 h1.52
  text "BOARD FINISH:" at 287.857,81.179 h1.52
  text "X" at 328.853,78.308 h1.52
  text "SILKSCREEN:" at 291.8,78.181 h1.52
  text "X" at 315.899,78.181 h1.52
  text "TOP" at 319.099,78.181 h1.52
  text "BOTTOM" at 332.079,78.181 h1.52
  text "SILKSCREEN COLOR:" at 291.8,73.94 h1.52
  text "X" at 315.872,73.94 h1.52
  text "WHITE" at 319.099,73.94 h1.52
  text "OTHER" at 332.079,73.94 h1.52
  text "SOLDER RESIST COLOR:" at 291.8,69.622 h1.52
  text "X" at 306.22,65.578 h1.52
  text "GREEN" at 309.447,65.578 h1.52
  text "BLUE" at 324.459,65.578 h1.52
  text "OTHER" at 338.124,65.578 h1.52
  text "IMMERSION GOLD (ENIG)" at 315.569,61.806 h1.52
  text "ENEPIG" at 349.542,61.722 h1.52
  text "SURFACE FINISH:" at 288.619,61.697 h1.52
  text "X" at 310.82,61.697 h1.52
  text "IMM. TIN/SILVER OR EQUIV" at 296.989,57.709 h1.52
  text "OTHER" at 333.349,57.709 h1.52
  text "ARRAY/PANEL:" at 288.492,54.305 h1.52
  text "CUT AND TRIM PER MECH LAYER 1" at 315.442,54.197 h1.52
  text "N.C. ROUTE" at 315.442,50.343 h1.52
  text "X" at 332.688,50.343 h1.52
  text "V. SCORE" at 337.438,50.343 h1.52
  text "CERTIFICATION:" at 288.492,46.863 h1.52
  text "MATERIALS AND WORKMANSHIP FOR ALL PCBS" at 306.907,46.863 h1.52
  text "TO MEET OR EXCEED THE REQUIREMENTS OF:" at 306.907,44.374 h1.52
  text "X" at 297.42,40.907 h1.52
  text "ANSI IPC-A-600F CLASS ->" at 300.951,40.907 h1.52
  text "X" at 342.583,40.907 h1.52
  text "2" at 345.604,40.907 h1.52
  text "1" at 337.603,40.869 h1.52
  text "3" at 354.596,40.869 h1.52
  text "X" at 297.473,36.856 h1.52
  text "UL 94V-0" at 300.951,36.856 h1.52
  text "X" at 318.097,36.856 h1.52
  text "RoHS" at 321.576,36.856 h1.52
  text "OTHER" at 337.944,36.856 h1.52
  text "PER ORDER" at 348.029,36.856 h1.52
  text "ADDITIONAL REQUIREMENTS:" at 288.492,33.274 h1.52
  text "NO" at 347.842,32.983 h1.52
  text "X" at 344.475,32.944 h1.52
  text "VIA TENTING" at 320.272,32.741 h1.52
  text "YES" at 337.645,32.599 h1.52
  text "IMPEDANCE CONTROL:" at 319.205,29.439 h1.52
  text "MICROSECTION:" at 290.696,29.413 h1.52
  text "YES" at 313.702,29.413 h1.52
  text "YES" at 343.792,29.413 h1.52
  text "X" at 357.965,29.235 h1.52
  text "NO" at 353.736,28.974 h1.52
  text "REQUIRED" at 335.279,25.092 h1.52
  text "BARE BOARD ELEC. TEST:" at 290.391,25.019 h1.52
  text "NONE" at 323.557,25.019 h1.52
  text "X" at 332.053,25.019 h1.52
  text "PER ORDER" at 350.316,25.019 h1.52
  text "MANUFACTURER'S UL:" at 290.391,21.031 h1.52
  text "RAIL" at 320.001,20.923 h1.52
  text "METAL" at 332.493,20.923 h1.52
  text "SILK" at 345.49,20.923 h1.52
  text "X" at 342.024,20.914 h1.52
M11 Gerber Information:
  lines w0.254: -7.417,-23.626 160.223,-23.626 ; -7.417,-18.462 160.274,-18.462 ; -7.417,-13.297 -7.417,-28.791 94.31,-28.791 160.274,-28.791 160.274,-13.297 -7.404,-13.297 -7.404,-28.791 32.614,-28.791 ; 62.56,-28.791 62.56,-13.297 ; 91.059,-18.462 91.059,-13.297 ; 108.712,-18.462 108.712,-13.297 ; 124.511,-28.956 124.511,-23.804
  text "BOARD #:" at 63.373,-16.637 h1.52
  text "ALL ARTWORK VIEWED FROM TOP SIDE" at -5.804,-16.654 h1.52
  text "REV:" at 92.405,-16.654 h1.52
  text ".PCB_Rev" at 99.809,-16.654 h1.52
  text "SVN REV:" at 113.69,-16.654 h1.52
  text ".VersionControl_RevNumber" at 126.543,-16.654 h1.52
  text ".PRJ_Number" at 75.692,-16.764 h1.52
  text "LAYER NAME=" at -5.804,-21.806 h1.52
  text ".plot_File_Name" at 9.779,-26.924 h1.52
  text "GENERATED    :" at 65.545,-26.924 h1.52
  text ".Print_Date" at 87.63,-26.924 h1.52
  text ".Print_Time" at 106.147,-26.924 h1.52
  text "PLOT NAME=" at -5.804,-27.034 h1.52
  text "TEXAS INSTRUMENTS" at 129.87,-27.034 h1.52
M12 Stackup:
  lines w0.127: 285.877,187.854 360.553,187.854 ; 285.877,190.376 360.553,190.376 ; 284.353,163.119 ccw(c285.166,163.119) 285.166,162.306 361.264,162.306 ccw(c361.264,163.119) 362.077,163.119 362.077,199.72 ccw(c361.264,199.72) 361.264,200.533 285.166,200.533 ccw(c285.166,199.72) 284.353,199.72 284.353,163.119
  text "Layer Stack Up Detail for: TIDA-00476-E1.PcbDoc" at 289.484,194.412 h1.32
  text "Layer" at 285.877,189.437 h0.58
  text "Gerber" at 301.824,189.437 h0.58
  text "Copper" at 309.984,189.437 h0.58
  text "Dielectric" at 319.098,189.437 h0.58
  text "Dielectric" at 328.62,189.437 h0.58
  text "Dielectric" at 340.504,189.437 h0.58
  text "Dielectric" at 350.027,189.437 h0.58
  text "Name" at 285.877,188.268 h0.58
  text "Document" at 301.824,188.268 h0.58
  text "Thickness" at 309.984,188.268 h0.58
  text "Height" at 319.098,188.268 h0.58
  text "Material" at 328.62,188.268 h0.58
  text "Constant" at 340.504,188.268 h0.58
  text "Type" at 350.027,188.268 h0.58
  text "Top Solder Mask" at 285.877,185.24 h0.81
  text "(.GTS)" at 301.824,185.24 h0.81
  text "0.4mil" at 319.098,185.24 h0.81
  text "Solder Resist" at 328.62,185.24 h0.81
  text "3.50" at 340.504,185.24 h0.81
  text "Top Layer" at 285.877,180.139 h0.81
  text "(.GTL)" at 301.824,180.139 h0.81
  text "1.4mil" at 309.984,180.139 h0.81
  text "59.2mil" at 319.098,177.588 h0.81
  text "FR-4 High Tg" at 328.62,177.588 h0.81
  text "4.80" at 340.504,177.588 h0.81
  text "Core" at 350.027,177.588 h0.81
  text "Bottom Layer" at 285.877,175.038 h0.81
  text "(.GBL)" at 301.824,175.038 h0.81
  text "1.4mil" at 309.984,175.038 h0.81
  text "Bottom Solder Mask" at 285.877,169.937 h0.81
  text "(.GBS)" at 301.824,169.937 h0.81
  text "0.4mil" at 319.098,169.937 h0.81
  text "Solder Resist" at 328.62,169.937 h0.81
  text "3.50" at 340.504,169.937 h0.81
M13 Component Bodies Top:
  text ".Layer_Name" at 16.739,-21.844 h1.52
M14 Component Bodies Bottom:
  text ".Layer_Name" at 16.129,-21.946 h1.52
M15 Courtyards Top:
  text ".Layer_Name" at 18.694,-21.666 h1.52
M16 Courtyards Bottom:
  text ".Layer_Name" at 16.383,-21.666 h1.52
Drill Drawing:
  text ".legend" at 47.371,95.504 h1.52
  text "Drill Table" at 47.625,92.583 h1.52
  text "DRILL TOLERANCE" at 47.161,90.209 h1.52
  text "FOR PTH +/- 3MIL" at 47.171,87.429 h1.52
  text "18mil drill:+0/-18mil" at 46.482,84.963 h1.52
  text ".Layer_Name" at 21.793,-21.488 h1.52

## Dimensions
0,0 to 0,49.911 on M2 Board Dimensions
0,0 to 85.09,0 on M2 Board Dimensions
0,-10.16 to 25.4,-10.16 on M2 Board Dimensions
